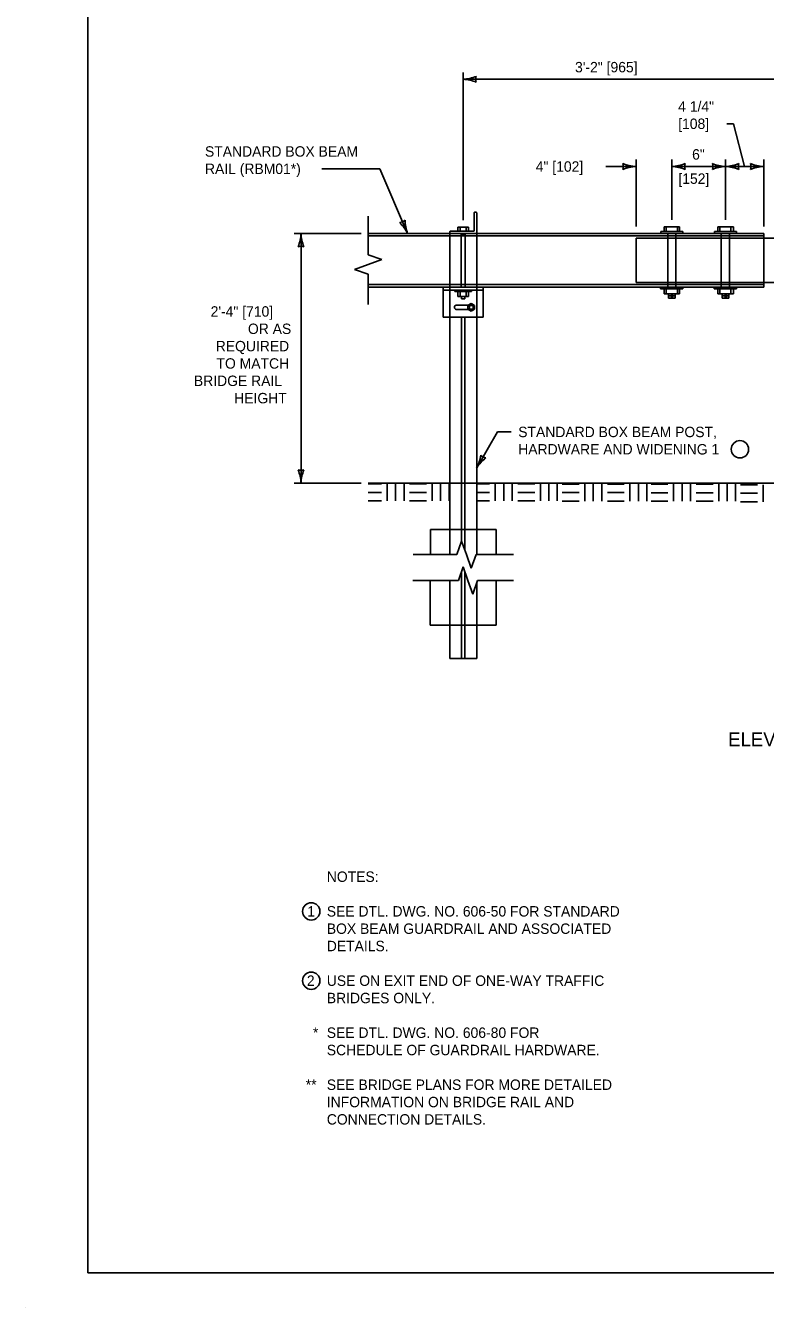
# Model space of a CAD drawing. Extents: x 49991.4 to 50021, y 49987.6 to 50011.4.
# Drawn here: x 49999.98 to 50004.24, y 49999.86 to 50007.26 of the extents above; entities that cross this region are included whole.
import ezdxf

# ---------------------------------------------------------------- set-up
doc = ezdxf.new("R2010")
doc.units = 0
for name, color, linetype in [('Level 1', 7, 'Continuous'), ('Level 2', 7, 'Continuous'), ('Level 3', 7, 'Continuous'), ('Level 4', 7, 'Continuous'), ('Level 6', 7, 'Continuous')]:
    doc.layers.add(name, color=color, linetype=linetype)

msp = doc.modelspace()

# ---------------------------------------------------------------- linework, layer by layer
at = {"layer": 'Level 1'}
for p, q in [((50002.5626, 50006.0724), (50002.5626, 50006.1766)), ((50002.5652, 50006.1793), (50002.5751, 50006.1793)), ((50002.5779, 50006.0599), (50002.5779, 50006.1766)), ((50002.4693, 50006.0932), (50002.4693, 50006.0697)), ((50002.5299, 50006.0932), (50002.4693, 50006.0932)), ((50002.4824, 50006.0932), (50002.4824, 50006.0697)), ((50002.5164, 50006.0932), (50002.5164, 50006.0697)), ((50002.5299, 50006.0932), (50002.5299, 50006.0697)), ((50003.6588, 50006.0683), (50003.6588, 50006.0962)), ((50003.6588, 50006.0962), (50003.7482, 50006.0962)), ((50003.6715, 50006.0683), (50003.6715, 50006.0962)), ((50003.7356, 50006.0683), (50003.7356, 50006.0962)), ((50003.7482, 50006.0683), (50003.7482, 50006.0962)), ((50003.9679, 50006.0683), (50003.9679, 50006.0962)), ((50003.9679, 50006.0962), (50004.0584, 50006.0962)), ((50003.9796, 50006.0683), (50003.9796, 50006.0962)), ((50004.0447, 50006.0683), (50004.0447, 50006.0962)), ((50004.0584, 50006.0683), (50004.0584, 50006.0962)), ((50004.2333, 50006.0572), (50001.9518, 50006.0572)), ((50002.4228, 50006.0671), (50002.4228, 50006.0599)), ((50002.5599, 50006.0697), (50002.4255, 50006.0697)), ((50002.4876, 50006.0572), (50002.5112, 50006.0572)), ((50003.766, 50006.0683), (50003.6409, 50006.0683)), ((50003.6409, 50006.0683), (50003.6409, 50006.0572)), ((50003.727, 50006.0572), (50003.6798, 50006.0572)), ((50003.766, 50006.0683), (50003.766, 50006.0572)), ((50003.9505, 50006.0683), (50004.0756, 50006.0683)), ((50003.9505, 50006.0683), (50003.9505, 50006.0572)), ((50003.9882, 50006.0572), (50004.0362, 50006.0572)), ((50004.0756, 50006.0683), (50004.0756, 50006.0572)), ((50004.2333, 50006.0572), (50004.2333, 50005.7481)), ((50004.3525, 50006.031), (50004.2333, 50006.031)), ((50004.2333, 50005.7481), (50001.9518, 50005.7481)), ((50002.3841, 50005.5753), (50002.3841, 50005.7481)), ((50002.6157, 50005.7295), (50002.3841, 50005.7295)), ((50002.4525, 50005.7232), (50002.4525, 50005.7295)), ((50002.5478, 50005.7232), (50002.4525, 50005.7232)), ((50002.4693, 50005.6936), (50002.4693, 50005.7232)), ((50002.4824, 50005.6936), (50002.4824, 50005.7232)), ((50002.5164, 50005.6936), (50002.5164, 50005.7232)), ((50002.5299, 50005.6936), (50002.5299, 50005.7232)), ((50002.5478, 50005.7232), (50002.5478, 50005.7295)), ((50002.6157, 50005.5753), (50002.6157, 50005.7481)), ((50003.6388, 50005.7481), (50003.6388, 50005.7373)), ((50003.6388, 50005.7373), (50003.7677, 50005.7373)), ((50003.6588, 50005.7373), (50003.6588, 50005.7095)), ((50003.6715, 50005.7373), (50003.6715, 50005.7095)), ((50003.727, 50005.7481), (50003.6798, 50005.7481)), ((50003.7356, 50005.7373), (50003.7356, 50005.7095)), ((50003.7482, 50005.7373), (50003.7482, 50005.7095)), ((50003.7677, 50005.7481), (50003.7677, 50005.7373)), ((50003.9486, 50005.7481), (50003.9486, 50005.7373)), ((50003.9486, 50005.7373), (50004.0773, 50005.7373)), ((50003.9679, 50005.7373), (50003.9679, 50005.7095)), ((50003.9796, 50005.7373), (50003.9796, 50005.7095)), ((50003.9882, 50005.7481), (50004.0362, 50005.7481)), ((50004.0447, 50005.7373), (50004.0447, 50005.7095)), ((50004.0584, 50005.7373), (50004.0584, 50005.7095)), ((50004.0773, 50005.7481), (50004.0773, 50005.7373)), ((50004.3525, 50005.774), (50004.2333, 50005.774)), ((50002.4596, 50005.6432), (50002.5053, 50005.6432)), ((50002.5299, 50005.6936), (50002.4693, 50005.6936)), ((50002.49, 50005.6936), (50002.49, 50005.6798)), ((50002.5089, 50005.6798), (50002.49, 50005.6798)), ((50002.5525, 50005.6432), (50002.5053, 50005.6432)), ((50002.5089, 50005.6936), (50002.5089, 50005.6798)), ((50002.5467, 50005.6535), (50002.5276, 50005.6425)), ((50002.5276, 50005.6205), (50002.5276, 50005.6425)), ((50002.5657, 50005.6425), (50002.5467, 50005.6535)), ((50002.5657, 50005.6205), (50002.5657, 50005.6425)), ((50003.6588, 50005.7095), (50003.7482, 50005.7095)), ((50003.6844, 50005.6842), (50003.6844, 50005.7095)), ((50003.7219, 50005.6969), (50003.6844, 50005.6969)), ((50003.7219, 50005.6842), (50003.6844, 50005.6842)), ((50003.711, 50005.7034), (50003.6975, 50005.7034)), ((50003.711, 50005.69), (50003.6975, 50005.69)), ((50003.7219, 50005.6842), (50003.7219, 50005.7095)), ((50003.9679, 50005.7095), (50004.0584, 50005.7095)), ((50003.993, 50005.6842), (50003.993, 50005.7095)), ((50004.0323, 50005.6969), (50003.993, 50005.6969)), ((50004.0323, 50005.6842), (50003.993, 50005.6842)), ((50004.0218, 50005.7034), (50004.0069, 50005.7034)), ((50004.0218, 50005.69), (50004.0069, 50005.69)), ((50004.0323, 50005.6842), (50004.0323, 50005.7095)), ((50002.6157, 50005.5753), (50002.3841, 50005.5753)), ((50002.4228, 50004.6177), (50002.4228, 50005.5753)), ((50002.4598, 50005.6197), (50002.5063, 50005.6197)), ((50002.5525, 50005.6197), (50002.5063, 50005.6197)), ((50002.5467, 50005.6095), (50002.5276, 50005.6205)), ((50002.5657, 50005.6205), (50002.5467, 50005.6095)), ((50002.5779, 50004.6177), (50002.5779, 50005.5753)), ((50001.9518, 50004.6177), (50006.6556, 50004.6177)), ((50001.9518, 50004.6122), (50002.0289, 50004.6122)), ((50002.0614, 50004.5147), (50002.0614, 50004.6122)), ((50002.1102, 50004.5147), (50002.1102, 50004.6122)), ((50002.1589, 50004.5147), (50002.1589, 50004.6122)), ((50002.1913, 50004.6122), (50002.289, 50004.6122)), ((50002.3215, 50004.5147), (50002.3215, 50004.6122)), ((50002.3701, 50004.5147), (50002.3701, 50004.6122)), ((50002.4189, 50004.5147), (50002.4189, 50004.6122)), ((50002.5779, 50004.6124), (50002.6526, 50004.6124)), ((50002.6851, 50004.5149), (50002.6851, 50004.6124)), ((50002.7339, 50004.5149), (50002.7339, 50004.6124)), ((50002.7826, 50004.5149), (50002.7826, 50004.6124)), ((50002.815, 50004.6124), (50002.9127, 50004.6124)), ((50002.9452, 50004.5149), (50002.9452, 50004.6124)), ((50002.9938, 50004.5149), (50002.9938, 50004.6124)), ((50003.0426, 50004.5149), (50003.0426, 50004.6124)), ((50003.0718, 50004.6114), (50003.1693, 50004.6114)), ((50003.2019, 50004.5139), (50003.2019, 50004.6114)), ((50003.2506, 50004.5139), (50003.2506, 50004.6114)), ((50003.2994, 50004.5139), (50003.2994, 50004.6114)), ((50003.3318, 50004.6114), (50003.4294, 50004.6114)), ((50003.462, 50004.5139), (50003.462, 50004.6114)), ((50003.5106, 50004.5139), (50003.5106, 50004.6114)), ((50003.5593, 50004.5139), (50003.5593, 50004.6114)), ((50003.5838, 50004.6103), (50003.6813, 50004.6103)), ((50003.7138, 50004.5128), (50003.7138, 50004.6103)), ((50003.7626, 50004.5128), (50003.7626, 50004.6103)), ((50003.8113, 50004.5128), (50003.8113, 50004.6103)), ((50003.8437, 50004.6103), (50003.9414, 50004.6103)), ((50003.9739, 50004.5128), (50003.9739, 50004.6103)), ((50004.0225, 50004.5128), (50004.0225, 50004.6103)), ((50004.0713, 50004.5128), (50004.0713, 50004.6103)), ((50004.1002, 50004.607), (50004.1977, 50004.607)), ((50004.2303, 50004.5095), (50004.2303, 50004.607)), ((50001.9518, 50004.5635), (50002.0289, 50004.5635)), ((50002.1913, 50004.5635), (50002.289, 50004.5635)), ((50002.5779, 50004.5637), (50002.6526, 50004.5637)), ((50002.815, 50004.5637), (50002.9127, 50004.5637)), ((50003.0718, 50004.5626), (50003.1693, 50004.5626)), ((50003.3318, 50004.5626), (50003.4294, 50004.5626)), ((50003.5838, 50004.5616), (50003.6813, 50004.5616)), ((50003.8437, 50004.5616), (50003.9414, 50004.5616)), ((50004.1002, 50004.5583), (50004.1977, 50004.5583)), ((50001.9518, 50004.5147), (50002.0289, 50004.5147)), ((50002.1913, 50004.5147), (50002.289, 50004.5147)), ((50002.5779, 50004.5149), (50002.6526, 50004.5149)), ((50002.815, 50004.5149), (50002.9127, 50004.5149)), ((50003.0718, 50004.5139), (50003.1693, 50004.5139)), ((50003.3318, 50004.5139), (50003.4294, 50004.5139)), ((50003.5838, 50004.5128), (50003.6813, 50004.5128)), ((50003.8437, 50004.5128), (50003.9414, 50004.5128)), ((50004.1002, 50004.5095), (50004.1977, 50004.5095)), ((49999.9766, 49999.8624), (49999.9766, 49999.8624))]:
    msp.add_line(p, q, dxfattribs=at)
msp.add_lwpolyline([(50008.6146, 50011.2628), (50000.3356, 50011.2628), (50000.3356, 50000.0624), (50008.6146, 50000.0624)], close=True, dxfattribs=at)
msp.add_circle((50002.5467, 50005.6315), 0.0191, dxfattribs=at)
for centre, radius, start, end in [((50002.5655, 50006.1768), 0.00265, 90, 180), ((50002.5756, 50006.1768), 0.00265, 0, 90), ((50002.4258, 50006.0673), 0.00265, 90, 180), ((50002.4258, 50006.06), 0.00265, 180, 270), ((50002.5599, 50006.0724), 0.00265, 270, 0), ((50002.5752, 50006.0599), 0.00265, 270, 0), ((50002.4616, 50005.6315), 0.0119, 99.33248, 261.45024), ((50002.5525, 50005.6315), 0.0118, 269.99831, 90.00169)]:
    msp.add_arc(centre, radius, start, end, dxfattribs=at)
at = {"layer": 'Level 2'}
for centre in [(50004.0962, 50004.8122), (50001.6235, 50002.1468), (50001.6235, 50001.7469)]:
    msp.add_circle(centre, 0.05, dxfattribs=at)
at = {"layer": 'Level 3'}
for p, q in [((50002.4997, 50006.1332), (50002.4997, 50006.9869)), ((50002.4997, 50006.9469), (50004.3525, 50006.9469)), ((50004.0598, 50006.6902), (50004.0205, 50006.6902)), ((50004.1232, 50006.4436), (50004.0598, 50006.6902)), ((50003.4971, 50006.0972), (50003.4971, 50006.4836)), ((50003.7035, 50006.1362), (50003.7035, 50006.4836)), ((50004.0132, 50006.1362), (50004.0132, 50006.4836)), ((50004.2333, 50006.0972), (50004.2333, 50006.4836)), ((50002.0186, 50006.4305), (50001.6842, 50006.4305)), ((50002.1793, 50006.0572), (50002.0186, 50006.4305)), ((50003.4971, 50006.4436), (50003.3237, 50006.4436)), ((50003.7035, 50006.4436), (50004.0132, 50006.4436)), ((50004.0132, 50006.4436), (50004.2333, 50006.4436)), ((50001.9118, 50006.0572), (50001.5248, 50006.0572)), ((50001.5648, 50006.0572), (50001.5648, 50004.6177)), ((50002.5779, 50004.7049), (50002.6983, 50004.9124)), ((50002.6983, 50004.9124), (50002.7776, 50004.9124)), ((50001.9118, 50004.6177), (50001.5248, 50004.6177))]:
    msp.add_line(p, q, dxfattribs=at)
for centre, radius, start, end in [((50002.4882, 50007.1796), 0.233, 272.82731, 292.07716), ((50002.4905, 50006.7248), 0.2223, 67.45601, 87.63952), ((50002.6279, 50006.9469), 0.0548, 162.13882, 197.86118), ((50003.5063, 50006.6657), 0.2223, 247.45601, 267.63952), ((50003.3689, 50006.4436), 0.0548, 342.13882, 17.86118), ((50003.692, 50006.6763), 0.233, 272.82731, 292.07716), ((50003.8317, 50006.4436), 0.0548, 162.13882, 197.86118), ((50004.0223, 50006.6657), 0.2223, 247.45601, 267.63952), ((50003.885, 50006.4436), 0.0548, 342.13882, 17.86118), ((50004.0017, 50006.6763), 0.233, 272.82731, 292.07716), ((50004.1414, 50006.4436), 0.0548, 162.13882, 197.86118), ((50004.2425, 50006.6657), 0.2223, 247.45601, 267.63952), ((50004.1051, 50006.4436), 0.0548, 342.13882, 17.86118), ((50003.5086, 50006.2109), 0.233, 92.82731, 112.07716), ((50003.6944, 50006.2214), 0.2223, 67.45601, 87.63952), ((50004.0247, 50006.2109), 0.233, 92.82731, 112.07716), ((50004.004, 50006.2214), 0.2223, 67.45601, 87.63952), ((50004.2448, 50006.2109), 0.233, 92.82731, 112.07716), ((50002.1286, 50006.175), 0.0548, 275.43903, 311.16139), ((50001.9701, 50005.9546), 0.233, 26.12752, 45.37737), ((50002.387, 50006.1367), 0.2223, 180.75622, 200.93973), ((50001.3427, 50006.0664), 0.2223, 337.45601, 357.63952), ((50001.7975, 50006.0687), 0.233, 182.82731, 202.07716), ((50001.5648, 50005.929), 0.0548, 72.13882, 107.86118), ((50002.3708, 50004.8118), 0.233, 332.71258, 351.96243), ((50002.7655, 50004.5856), 0.2223, 127.34128, 147.52479), ((50002.6422, 50004.8159), 0.0548, 222.02409, 257.74645), ((50001.5648, 50004.7459), 0.0548, 252.13882, 287.86118), ((50001.3321, 50004.6062), 0.233, 2.82731, 22.07716), ((50001.7869, 50004.6085), 0.2223, 157.45601, 177.63952)]:
    msp.add_arc(centre, radius, start, end, dxfattribs=at)
at = {"layer": 'Level 4'}
for p, q in [((50004.2333, 50006.0428), (50001.9518, 50006.0428)), ((50002.4228, 50005.7481), (50002.4228, 50006.0572)), ((50002.4876, 50006.0572), (50002.4876, 50005.7626)), ((50002.4876, 50006.0521), (50002.5112, 50006.0521)), ((50002.4876, 50006.0479), (50002.5112, 50006.0479)), ((50002.5112, 50005.7626), (50002.5112, 50006.0572)), ((50002.5779, 50005.7481), (50002.5779, 50006.0572)), ((50004.2333, 50006.031), (50003.4971, 50006.031)), ((50003.4971, 50006.031), (50003.4971, 50005.774)), ((50003.6798, 50006.0428), (50003.6798, 50006.0572)), ((50003.6798, 50006.0428), (50003.6798, 50005.7626)), ((50003.727, 50006.0428), (50003.727, 50006.0572)), ((50003.727, 50006.0428), (50003.727, 50005.7626)), ((50003.9882, 50006.0572), (50003.9882, 50005.7481)), ((50004.0362, 50006.0572), (50004.0362, 50005.7481)), ((50004.2333, 50005.7626), (50001.9518, 50005.7626)), ((50002.4228, 50005.7481), (50002.4228, 50005.5753)), ((50002.4876, 50005.7481), (50002.4876, 50005.7626)), ((50002.5112, 50005.7481), (50002.5112, 50005.7626)), ((50002.5779, 50005.7481), (50002.5779, 50005.5753)), ((50004.2333, 50005.774), (50003.4971, 50005.774)), ((50003.6798, 50005.7626), (50003.6798, 50005.7481)), ((50003.727, 50005.7626), (50003.727, 50005.7481)), ((50002.4895, 50005.5753), (50002.4895, 50004.2784)), ((50002.5104, 50005.5753), (50002.5104, 50004.2286)), ((50002.4228, 50004.6177), (50002.4228, 50004.2047)), ((50002.5779, 50004.6177), (50002.5779, 50004.2047)), ((50002.3107, 50004.3493), (50002.4229, 50004.3493)), ((50002.3107, 50004.2047), (50002.3107, 50004.3493)), ((50002.4229, 50004.3493), (50002.578, 50004.3493)), ((50002.578, 50004.3493), (50002.6902, 50004.3493)), ((50002.6902, 50004.2047), (50002.6902, 50004.3493)), ((50002.4895, 50004.1042), (50002.4895, 50003.6058)), ((50002.5104, 50004.1039), (50002.5104, 50003.6058)), ((50002.3106, 50004.0553), (50002.3106, 50003.7969)), ((50002.4228, 50004.0553), (50002.4228, 50003.6058)), ((50002.5779, 50004.0402), (50002.5779, 50003.6058)), ((50002.6901, 50004.0553), (50002.6901, 50003.7969)), ((50002.6901, 50003.7969), (50002.3106, 50003.7969)), ((50002.5779, 50003.6058), (50002.4228, 50003.6058))]:
    msp.add_line(p, q, dxfattribs=at)
msp.add_circle((50002.5467, 50005.6315), 0.0112, dxfattribs=at)
at = {"layer": 'Level 6'}
for p, q in [((50001.9518, 50006.1572), (50001.9518, 50005.9344)), ((50002.0307, 50005.9065), (50001.9518, 50005.9344)), ((50001.9518, 50005.8786), (50001.8727, 50005.8504)), ((50002.0307, 50005.9065), (50001.9518, 50005.8786)), ((50001.9518, 50005.8225), (50001.8727, 50005.8504)), ((50001.9518, 50005.8225), (50001.9518, 50005.6481)), ((50002.4912, 50004.2832), (50002.4636, 50004.2047)), ((50002.4912, 50004.2832), (50002.5188, 50004.2047)), ((50002.2107, 50004.2047), (50002.4636, 50004.2047)), ((50002.5188, 50004.2047), (50002.5469, 50004.1263)), ((50002.5745, 50004.2047), (50002.5469, 50004.1263)), ((50002.5745, 50004.2047), (50002.7902, 50004.2047)), ((50002.4999, 50004.1338), (50002.4723, 50004.0553)), ((50002.4999, 50004.1338), (50002.5275, 50004.0553)), ((50002.2106, 50004.0553), (50002.4723, 50004.0553)), ((50002.5275, 50004.0553), (50002.5556, 50003.9769)), ((50002.5832, 50004.0553), (50002.5556, 50003.9769)), ((50002.5832, 50004.0553), (50002.7901, 50004.0553))]:
    msp.add_line(p, q, dxfattribs=at)

# ---------------------------------------------------------------- texts
at = {"layer": 'Level 2'}
for s, height, p in [('3\'-2" [965]', 0.06, (50003.1453, 50006.9869)), ('4 1/4"', 0.06, (50003.7401, 50006.7602)), ('[108]', 0.06, (50003.7401, 50006.6602)), ('STANDARD BOX BEAM', 0.06, (50001.0109, 50006.5005)), ('6"', 0.06, (50003.8204, 50006.4836)), ('RAIL (RBM01*)', 0.06, (50001.0109, 50006.4005)), ('4" [102]', 0.06, (50002.9187, 50006.4136)), ('[152]', 0.06, (50003.7412, 50006.3436)), ('2\'-4" [710]', 0.06, (50001.0436, 50005.5775)), ('OR AS', 0.06, (50001.2587, 50005.4775)), ('REQUIRED', 0.06, (50001.073, 50005.3775)), ('TO MATCH', 0.06, (50001.0774, 50005.2775)), ('BRIDGE RAIL', 0.06, (50000.9472, 50005.1775)), ('HEIGHT', 0.06, (50001.1795, 50005.0775)), ('STANDARD BOX BEAM POST, ', 0.06, (50002.8176, 50004.8824)), ('HARDWARE AND WIDENING 1', 0.06, (50002.8176, 50004.7824)), ('ELEVATION', 0.08, (50004.0287, 50003.0994)), ('NOTES:', 0.06, (50001.7135, 50002.3169)), ('1', 0.06, (50001.6008, 50002.1168)), ('SEE DTL. DWG. NO. 606-50 FOR STANDARD', 0.06, (50001.7135, 50002.1169)), ('BOX BEAM GUARDRAIL AND ASSOCIATED ', 0.06, (50001.7135, 50002.0169)), ('DETAILS.', 0.06, (50001.7135, 50001.9169)), ('2', 0.06, (50001.5984, 50001.7169)), ('USE ON EXIT END OF ONE-WAY TRAFFIC', 0.06, (50001.7135, 50001.7169)), ('BRIDGES ONLY.', 0.06, (50001.7135, 50001.6169)), ('*', 0.06, (50001.6337, 50001.4169)), ('SEE DTL. DWG. NO. 606-80 FOR ', 0.06, (50001.7135, 50001.4169)), ('SCHEDULE OF GUARDRAIL HARDWARE.', 0.06, (50001.7135, 50001.3169)), ('**', 0.06, (50001.5921, 50001.1169)), ('SEE BRIDGE PLANS FOR MORE DETAILED', 0.06, (50001.7135, 50001.1169)), ('INFORMATION ON BRIDGE RAIL AND', 0.06, (50001.7135, 50001.0169)), ('CONNECTION DETAILS.', 0.06, (50001.7135, 50000.9169))]:
    msp.add_text(s, height=height, dxfattribs=at).set_placement(p)

doc.saveas('drawing.dxf')
